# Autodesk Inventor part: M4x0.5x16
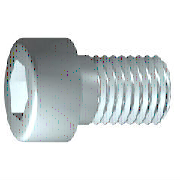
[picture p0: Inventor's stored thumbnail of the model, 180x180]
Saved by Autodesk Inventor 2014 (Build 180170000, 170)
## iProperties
Created: 2014-07
Part Number: M4x0.5x16
Material: 강, 연강
Description: 6각머리 태핑 나사
Document SubType Name: Modeling
Standard: KS B 1003
Designer: KYOUNG IL JANG
Standards Organization: KS
Language: ko-KR
Size Designation: M 4 x 16
Categories: <MemberInstance><Categories><Category DisplayName="조임쇠" InternalName="e4da775c-781d-43d5-af7c-5136215cf5a6" Mnemonic="FSTN"><Category DisplayName="볼트" InternalN
Density: 1 g/cm^3
Appearance: 강철
Company: 한국ATC센터
IsCustomPart: 1
Author: KYOUNG IL JANG
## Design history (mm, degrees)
sketch "스케치1"
  geometry: L1 (-1, 0)-(16, 0); L2 (16, 0)-(16, 2); L3 (16, 2)-(1.75, 2); L4 (1.75, 2)-(1.32, 2); L5 (1.32, 2)-(0, 2); L6 (0, 2)-(0, 3.5); L7 (0, 3.5)-(-4, 3.5); L8 (-4, 3.5)-(-4, 1.732); L9 (-4, 1.732)-(-2, 1.732); L10 (-2, 1.732)-(-1, 0); L11 (-8, 0)-(20, 0) reference; L12 (0, -0.7)-(0, 4.2) reference; L13 (1.75, 2)-(0, 2)
  constraints: 22 end point, 6 parallel, 2 collinear, 2 perpendicular, 1 horizontal, 1 point on line
  dimensions: "d1" = 14.25 distance from line of L3.end L2 (= GEL); "d2" = 0.42952 distance of L4.end L3.end (computed from GAL); "d3" = 4 distance between parallel lines of L8 L6 (= KOH); "d4" = 2 distance of L8.end L9.end (= INTI); "d5" = 60 deg angle of L10 L1; "d6" = 4 diameter of L3 L1 (= GD); "d7" = 4 diameter of L5 L1 (= BDM); "d8" = 3.4641 diameter of L9 L1 (= 1.1547 x SW); "d9" = 7 diameter of L7 L1 (= KOD); "d26" = 16 distance between parallel lines of L12 L2 (= NLG)
revolve "본체" sketch "스케치1" stored, may be unused: angle "d10" = 90 deg
sketch "스케치2"
  geometry: L1 (0, -4.9)-(0, 4.9) reference; L2 (-4.9, 0)-(4.9, 0) reference; L3 (1.732, 0)-(0.866, -1.5); L4 (0.866, -1.5)-(-0.866, -1.5); L5 (-0.866, -1.5)-(-1.732, 0); L6 (-1.732, 0)-(-0.866, 1.5); L7 (-0.866, 1.5)-(0.866, 1.5); L8 (0.866, 1.5)-(1.732, 0); 2 further points
  constraints: 12 end point, 1 coincident, 1 horizontal alignment, 1 point on line, 12 other
extrude "슬롯" join sketch "스케치2" stored distance "d11" = 10; taper "d12" = 0 deg
workplane "Work Plane1"
fillet "Fillet2" dims "d30" = 0.1 (= R)
body "Solid1"
fillet "모깎기1" dims "d17" = 0.4 (= RR)
feature "스레드" dims "d13" = 14.25 (= GEL), "d14" = 0
chamfer "모따기1" distance "d15" = 0.42941 (= -0.5 x SPD + 0.5 x GD); stored, may be unused: second distance "d16" = 0.42941 (= GUL), angle "d27" = 45 deg
other parameters: "GD" = 4 (= NND) [user parameter; used in 2 equation terms], "NLG" = 16 [user parameter; used in 1 equation term], "GEL" = 14.25 [user parameter; used in 2 equation terms], "KOD" = 7 [user parameter; used in 1 equation term], "KOH" = 4 [user parameter; used in 1 equation term], "INTI" = 2 [user parameter; used in 1 equation term], "GAL" = 0.42941 (= 0.61345 x PTC) [user parameter; used in 1 equation term], "GUL" = 0.42941 (= 0.61345 x PTC) [user parameter; used in 1 equation term], "BDM" = 4 (= NND) [user parameter; used in 1 equation term], "SW" = 3 [user parameter; used in 2 equation terms], "RR" = 0.4 [user parameter; used in 1 equation term], "SPD" = 3.14117 (= NND - 1.2269 x PTC) [user parameter; used in 1 equation term], "d19" = 0, "d28" = 0, "d29" = 0, "R" = 0.1 [user parameter; used in 1 equation term], "PHH" = 0.2 [user parameter], "GD1" = 3.14117 (= THREADDIA - 1.2269 x PTC) [user parameter], "THREADDIA" = 4 [user parameter; used in 1 equation term], "FAWI" = 45 deg [user parameter], "TPU" = 14.28571 (computed from PTC) [user parameter], "PTC" = 0.7 [user parameter; used in 5 equation terms], "NND" = 4 [user parameter; used in 3 equation terms], "TOA" = 30 deg [user parameter], "E0" = 3.465 (= 1.155 x SW) [user parameter]
